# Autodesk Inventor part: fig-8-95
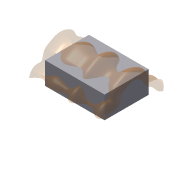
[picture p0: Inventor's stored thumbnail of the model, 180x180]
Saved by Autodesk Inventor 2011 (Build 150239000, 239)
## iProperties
Shininess: 64.0
Length Units: 11269
Angle Units: 11279
Time Units: 11290
Mass Units: 11283
Length Display Precision: 3
Angle Display Precision: 2
Compacted: True
Part Number: fig-8-95
Document SubType Name: Modeling
Created: 2002-12
Designer: deepak
Density: 1 g/cm^3
Density: 0.0
Volumn: 0.0
Area: 0.0
PropertySet Name: Model Information
Control State: 0
Master: False
Checked Out: False
Author: deepak
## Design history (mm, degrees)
sketch "Sketch1"
  geometry: L1 (-34.987, 25.636)-(31.934, 25.636); L2 (31.934, 25.636)-(31.934, -23.728); L3 (31.934, -23.728)-(-34.987, -23.728); L4 (-34.987, -23.728)-(-34.987, 25.636)
  constraints: 8 end point, 2 parallel, 1 horizontal, 1 perpendicular
extrude "Extrusion1" new body sketch "Sketch1" distance "d0" = 25; taper "d1" = 0 deg
sketch "Sketch2"
  geometry: 14 further points
  constraints: 14 other
workplane "Work Plane1"
sketch "Sketch3"
  geometry: 8 further points
  constraints: 8 other
feature "SweepSrf1" sketch "Sketch3" dims "d2" = 0
body "Solid1"
body "Srf1"
